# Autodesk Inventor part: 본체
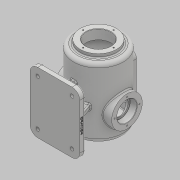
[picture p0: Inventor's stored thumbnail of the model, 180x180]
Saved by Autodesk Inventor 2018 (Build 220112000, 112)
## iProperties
Created: 2021-11
Part Number: 본체
Material: 일반
Document SubType Name: Modeling
Designer: home
Density: 1 g/cm^3
Appearance: 기본값
Author: home
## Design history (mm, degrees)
sketch "스케치1"
  geometry: L1 (0, 0)-(65, 0); L2 (65, 0)-(65, -175.993); L3 (0, -200)-(0, 0); L4 (0, -100)-(0, -200); A1 r 100 centre (0, -100) between (0, -200) and (65, -175.993)
  constraints: 8 end point, 2 parallel, 2 point on circle, 1 centre point, 1 coincident, 1 horizontal, 1 midpoint, 1 perpendicular, 1 tangent
  dimensions: "d3" = 100 radius of A1; "d4" = 65 distance between parallel lines of L2 L3
revolve "회전1" sketch "스케치1" stored, may be unused: angle "d5" = 90 deg
sketch "스케치2"
  geometry: C1 r 47.5 at (0, 0); 1 further point
  constraints: 1 centre point, 1 coincident
  dimensions: "d6" = 95 diameter of C1
extrude "돌출1" join sketch "스케치2" distance "d7" = 10; taper "d8" = 0 deg
node "작업 평면1"
sketch "스케치3"
  geometry: L1 (30, -40)-(-30, -40); L2 (-30, -40)-(-30, -160); L3 (-30, -160)-(30, -160); L4 (30, -160)-(30, -40); L5 (47.5, 10)-(-47.5, 10) reference; 2 further points
  constraints: 8 end point, 2 parallel, 1 horizontal, 1 midpoint, 1 perpendicular, 1 vertical alignment
  dimensions: "d10" = 60 distance of L3.end L2.end; "d11" = 120 distance of L2.end L1.end; "d12" = 50 distance between parallel lines of L5 L1
extrude "돌출2" join sketch "스케치3" stored distance "d13" = 10; taper "d14" = 0 deg
sketch "스케치4"
  geometry: L1 (-30, 160)-(-30, 40) reference; L2 (-30, 100)-(30, 100); L3 (30, 160)-(30, 40) reference; L4 (0, 40)-(0, 160); L5 (-24, 45)-(0, 45); L6 (-25, 100)-(-25, 130); L7 (-30, 40)-(30, 40) reference; L8 (25, 100)-(25, 126); L9 (0, 155)-(-18, 155); L10 (30, 160)-(-30, 160) reference; 1 further point
  constraints: 12 end point, 4 point on line, 3 vertical, 2 midpoint, 1 horizontal, 1 perpendicular
  dimensions: "d15" = 5 distance between parallel lines of L1 L6; "d16" = 5 distance between parallel lines of L7 L5; "d24" = 5 distance between parallel lines of L10 L9; "d25" = 5 distance between parallel lines of L3 L8
hole "구멍1" sketch "스케치4" at (-25, 100), (0, 45), (25, 100), (0, 155) diameter "d17" = 3.242; stored, may be unused: countersink angle "d21" = 90 deg, drill point angle "d23" = 118 deg; dims "d18" = 9, "d19" = 4, "d20" = 2, "d22" = 11
node "작업 평면2"
sketch "스케치5"
  geometry: L1 (70, -160)-(70, -40) reference; L2 (70, -98.379)-(70, -101.621) reference; L3 (70, -100)-(100, -100); C1 r 40 at (0, -117); 1 further point
  constraints: 2 end point, 1 centre point, 1 horizontal, 1 midpoint, 1 vertical alignment
  dimensions: "d28" = 80 diameter of C1; "d29" = 17 distance from line of C1.centre L3
extrude "돌출3" join sketch "스케치5" stored distance "d30" = 10; taper "d31" = 0 deg
sketch "스케치6" dims "d32" = 65
  geometry: L1 (0, 0)-(0, 32.5); 1 further point
  constraints: 2 end point, 1 vertical, 1 vertical alignment, 2 other
  dimensions: "d33" = 117 distance from line of point (117, 0) L1; "d34" = 121.43002 distance of point (117, 0) L1.end
hole "구멍2" sketch "스케치6" at (0, 32.5) diameter "d35" = 3.242; stored, may be unused: countersink angle "d39" = 90 deg, drill point angle "d41" = 118 deg; dims "d36" = 11, "d37" = 4, "d38" = 2, "d40" = 13
hole "구멍3" diameter "d47" = 42; stored, may be unused: countersink angle "d51" = 90 deg, drill point angle "d53" = 0 deg; dims "d45" = 10, "d46" = 10, "d48" = 42, "d49" = 52, "d50" = 18, "d52" = 60
sketch "스케치7"
  geometry: L1 (0, 10)-(0, -190); L2 (0, 10)-(32.5, 10); L3 (32.5, 10)-(32.5, -15); L4 (65, 0)-(65, -175.993) reference; L5 (58.532, -15)-(150.532, -15); L6 (32.5, -15)-(55, -15); L7 (55, -15)-(55, -171.239); A1 r 100 centre (0, -100) between (-65, -175.993) and (65, -175.993) reference; A2 r 90 centre (0, -100) between (0, -190) and (55, -171.239); 1 further point
  constraints: 12 end point, 2 parallel, 2 perpendicular, 2 point on circle, 1 centre point, 1 horizontal, 1 vertical
  dimensions: "d54" = 10 radial gap between concentric circles of A1 A2; "d61" = 200 distance of L1.start L1.end; "d63" = 10 distance between parallel lines of L7 L4; "d64" = 32.5 distance between parallel lines of L3 L4; "d65" = 130 diameter of L4 L1; "d66" = 0 distance between parallel lines of L6 L5; "d67" = 25 distance between parallel lines of L2 L5; "d68" = 85.53249 distance from line of L5.end L4; "d69" = 6.46751 distance from line of L5.start L4
revolve "회전2" sketch "스케치7" stored, may be unused: angle "d70" = 90 deg
sketch "스케치8" dims "d71" = 80
  geometry: L1 (0, 0)-(0, 40); 1 further point
  constraints: 2 end point, 1 coincident, 1 vertical, 1 vertical alignment, 2 other
hole "구멍4" sketch "스케치8" at (0, 40) diameter "d72" = 3.242; stored, may be unused: countersink angle "d76" = 90 deg, drill point angle "d78" = 118 deg; dims "d73" = 11, "d74" = 52, "d75" = 18, "d77" = 13
sketch "스케치9"
  geometry: L1 (-20, 50)-(20, 50); L2 (20, 50)-(20, 150); L3 (20, 150)-(-20, 150); L4 (-20, 150)-(-20, 50); L5 (-30, 160)-(-30, 40) reference; L6 (30, 40)-(30, 160) reference; L7 (30, 160)-(-30, 160) reference; L8 (-30, 40)-(30, 40) reference; 1 further point
  constraints: 8 end point, 2 parallel, 1 horizontal, 1 perpendicular
  dimensions: "d82" = 10 distance between parallel lines of L5 L4; "d83" = 10 distance between parallel lines of L6 L2; "d84" = 10 distance between parallel lines of L7 L3; "d85" = 10 distance between parallel lines of L8 L1
extrude "돌출4" cut sketch "스케치9" distance "d86" = 30; taper "d87" = 0 deg
node "작업 평면3"
sketch "스케치10"
  geometry: L1 (65, -20)-(-65, -20); L2 (-65, -180)-(65, -180); L3 (65, -180)-(65, -20); L4 (-30, -160)-(30, -160) reference; L5 (47.5, 10)-(-47.5, 10) reference; 3 further points; 1 other entity
  constraints: 6 end point, 2 horizontal, 2 midpoint, 1 parallel, 1 vertical, 1 vertical alignment, 3 other
  dimensions: "d89" = 130 distance of L2.end L2.start; "d90" = 160 distance of L2.start L1.end; "d91" = 30 distance between parallel lines of L5 L1
extrude "돌출5" join sketch "스케치10" distance "d92" = 14; taper "d93" = 0 deg
node "작업 평면4"
sketch "스케치11"
  geometry: L1 (0, 14)-(130, 14) reference; L2 (15, 14)-(115, 14); L3 (15, 14)-(31.191, 58.485); L4 (115, 14)-(98.809, 58.485); L5 (115, 14)-(152.246, 14); A1 r 65 centre (65, 114) between (31.191, 58.485) and (98.809, 58.485) reference; 2 further points
  constraints: 8 end point, 2 point on circle, 2 point on line, 1 horizontal, 1 midpoint, 1 vertical alignment
  dimensions: "d95" = 100 distance of L2.start L2.end; "d96" = 110 deg angle of L1 L3; "d97" = 110 deg angle of L5 L4
extrude "돌출6" join sketch "스케치11" stored distance "d98" = 14; taper "d99" = 0 deg
sketch "스케치12"
  geometry: L1 (-100, -40)-(-65, -52.739); L2 (-65, 0)-(-65, -175.993) reference; 1 further point
  constraints: 2 end point, 1 point on line
feature "리브1" sketch "스케치12" dims "d102" = 1, "d103" = 14, "d104" = 0, "d105" = 0, "d106" = 1, "d107" = 1
fillet "모깎기1" dims "d108" = 20, "d145" = 10, "d146" = 5, "d147" = 15
hole "구멍5" diameter "d111" = 9; stored, may be unused: countersink angle "d115" = 90 deg, drill point angle "d117" = 0 deg; dims "d109" = 10, "d110" = 10, "d112" = 11, "d113" = 18, "d114" = 2, "d116" = 42
hole "구멍6" diameter "d120" = 9; stored, may be unused: countersink angle "d124" = 90 deg, drill point angle "d126" = 0 deg; dims "d118" = 10, "d119" = 10, "d121" = 11, "d122" = 18, "d123" = 2, "d125" = 42
hole "구멍7" diameter "d129" = 9; stored, may be unused: countersink angle "d133" = 90 deg, drill point angle "d135" = 0 deg; dims "d127" = 10, "d128" = 10, "d130" = 11, "d131" = 18, "d132" = 2, "d134" = 42
hole "구멍8" diameter "d138" = 9; stored, may be unused: countersink angle "d142" = 90 deg, drill point angle "d144" = 0 deg; dims "d136" = 10, "d137" = 10, "d139" = 11, "d140" = 18, "d141" = 2, "d143" = 42
chamfer "모따기1" distance "d148" = 1; stored, may be unused: second distance "d149" = 2, angle "d150" = 45 deg
fillet "모깎기2" dims "d151" = 3, "d155" = 0.3
sketch "스케치13"
  geometry: L1 (0, 0)-(120, 0) reference; L2 (120, 14)-(0, 14) reference; 3 further points
  constraints: 1 midpoint, 1 vertical alignment, 1 other
  dimensions: "d152" = 5 distance from line of L1 point (60, 5)
feature "엠보싱1" sketch "스케치13" dims "d3" = 100, "d4" = 65, "d12" = 50, "d153" = 0.5, "d154" = 0
node "솔리드1"
pattern_circular "원형 패턴1" dims angle "d43" = 360 deg
pattern_circular "원형 패턴2" dims angle "d80" = 360 deg
mirror "미러1"
mirror "미러2"
other parameters: "d26" = -75, "d88" = -114
